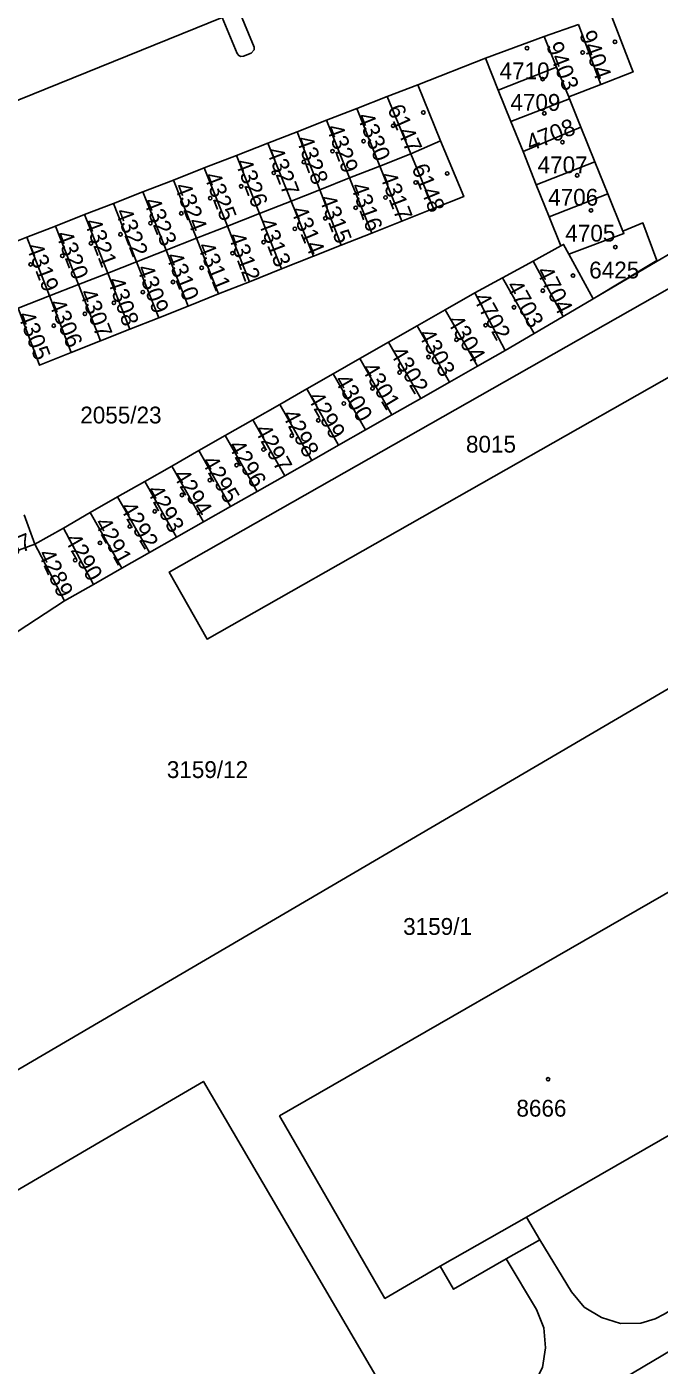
# Model space of a CAD drawing. Extents: x -564952 to -564307, y -1202373 to -1201847.
# Drawn here: x -564872.3 to -564808.4, y -1202052.1 to -1201916.7 of the extents above; entities that cross this region are included whole.
import ezdxf

# ---------------------------------------------------------------- set-up
doc = ezdxf.new("R2010")
doc.units = 0
for name, color, linetype in [('Hranice parcel', 7, 'Continuous'), ('Parcelní čísla', 7, 'Continuous'), ('Vnitřní kresba', 7, 'Continuous'), ('Značky budov', 7, 'Continuous')]:
    doc.layers.add(name, color=color, linetype=linetype)

msp = doc.modelspace()

# ---------------------------------------------------------------- linework, layer by layer
at = {"layer": 'Hranice parcel'}
for p, q in [((-564816.53, -1201916.48), (-564820.03, -1201917.7)), ((-564820.03, -1201917.7), (-564825.94, -1201919.91)), ((-564820.03, -1201917.7), (-564818.76, -1201920.82)), ((-564825.94, -1201919.91), (-564832.8, -1201922.58)), ((-564824.65, -1201923.12), (-564825.94, -1201919.91)), ((-564818.76, -1201920.82), (-564824.65, -1201923.12)), ((-564818.76, -1201920.82), (-564817.71, -1201923.35)), ((-564832.8, -1201922.58), (-564835.87, -1201923.78)), ((-564832.8, -1201922.58), (-564830.48, -1201928.24)), ((-564817.53, -1201923.8), (-564814.3, -1201922.55)), ((-564835.87, -1201923.78), (-564838.95, -1201924.98)), ((-564833.48, -1201929.57), (-564835.87, -1201923.78)), ((-564823.37, -1201926.3), (-564824.65, -1201923.12)), ((-564817.47, -1201924.01), (-564823.37, -1201926.3)), ((-564817.71, -1201923.35), (-564817.53, -1201923.8)), ((-564817.47, -1201924.01), (-564817.53, -1201923.8)), ((-564816.31, -1201926.87), (-564817.47, -1201924.01)), ((-564838.95, -1201924.98), (-564842.02, -1201926.18)), ((-564836.63, -1201930.81), (-564838.95, -1201924.98)), ((-564842.02, -1201926.18), (-564844.98, -1201927.33)), ((-564839.68, -1201932.01), (-564842.02, -1201926.18)), ((-564822.15, -1201929.34), (-564823.37, -1201926.3)), ((-564844.98, -1201927.33), (-564847.96, -1201928.5)), ((-564842.7, -1201933.2), (-564844.98, -1201927.33)), ((-564816.31, -1201926.87), (-564822.15, -1201929.34)), ((-564814.89, -1201930.38), (-564816.31, -1201926.87)), ((-564847.96, -1201928.5), (-564851.11, -1201929.73)), ((-564845.6, -1201934.34), (-564847.96, -1201928.5)), ((-564833.48, -1201929.57), (-564830.48, -1201928.24)), ((-564820.81, -1201932.69), (-564822.15, -1201929.34)), ((-564851.11, -1201929.73), (-564854.37, -1201931)), ((-564848.78, -1201935.59), (-564851.11, -1201929.73)), ((-564836.63, -1201930.81), (-564839.68, -1201932.01)), ((-564833.48, -1201929.57), (-564836.63, -1201930.81)), ((-564834.41, -1201936.38), (-564836.63, -1201930.81)), ((-564831.2, -1201935.1), (-564833.48, -1201929.57)), ((-564814.89, -1201930.38), (-564820.81, -1201932.69)), ((-564791.55, -1201930.35), (-564815.05, -1201944.22)), ((-564813.58, -1201933.62), (-564814.89, -1201930.38)), ((-564857.49, -1201932.22), (-564860.57, -1201933.42)), ((-564854.37, -1201931), (-564857.49, -1201932.22)), ((-564855.16, -1201938.1), (-564857.49, -1201932.22)), ((-564852.04, -1201936.87), (-564854.37, -1201931)), ((-564839.68, -1201932.01), (-564842.7, -1201933.2)), ((-564837.45, -1201937.59), (-564839.68, -1201932.01)), ((-564860.57, -1201933.42), (-564863.55, -1201934.59)), ((-564858.23, -1201939.31), (-564860.57, -1201933.42)), ((-564842.7, -1201933.2), (-564845.6, -1201934.34)), ((-564840.52, -1201938.81), (-564842.7, -1201933.2)), ((-564819.5, -1201935.94), (-564820.81, -1201932.69)), ((-564863.55, -1201934.59), (-564866.47, -1201935.72)), ((-564861.21, -1201940.48), (-564863.55, -1201934.59)), ((-564845.6, -1201934.34), (-564848.78, -1201935.59)), ((-564843.35, -1201939.93), (-564845.6, -1201934.34)), ((-564813.58, -1201933.62), (-564819.5, -1201935.94)), ((-564812.05, -1201937.38), (-564813.58, -1201933.62)), ((-564866.47, -1201935.72), (-564869.41, -1201936.87)), ((-564864.14, -1201941.63), (-564866.47, -1201935.72)), ((-564848.78, -1201935.59), (-564852.04, -1201936.87)), ((-564846.56, -1201941.21), (-564848.78, -1201935.59)), ((-564831.2, -1201935.1), (-564834.41, -1201936.38)), ((-564818.32, -1201938.88), (-564819.5, -1201935.94)), ((-564869.41, -1201936.87), (-564872.31, -1201938.01)), ((-564867.09, -1201942.79), (-564869.41, -1201936.87)), ((-564852.04, -1201936.87), (-564855.16, -1201938.1)), ((-564849.81, -1201942.5), (-564852.04, -1201936.87)), ((-564837.45, -1201937.59), (-564840.52, -1201938.81)), ((-564834.41, -1201936.38), (-564837.45, -1201937.59)), ((-564872.31, -1201938.01), (-564875.4, -1201939.21)), ((-564870.03, -1201943.94), (-564872.31, -1201938.01)), ((-564855.16, -1201938.1), (-564858.23, -1201939.31)), ((-564852.92, -1201943.74), (-564855.16, -1201938.1)), ((-564840.52, -1201938.81), (-564843.35, -1201939.93)), ((-564821.14, -1201940.42), (-564818.32, -1201938.88)), ((-564858.23, -1201939.31), (-564861.21, -1201940.48)), ((-564855.99, -1201944.96), (-564858.23, -1201939.31)), ((-564843.35, -1201939.93), (-564846.56, -1201941.21)), ((-564815.05, -1201944.22), (-564817.52, -1201939.7)), ((-564864.14, -1201941.63), (-564867.09, -1201942.79)), ((-564861.21, -1201940.48), (-564864.14, -1201941.63)), ((-564861.89, -1201947.31), (-564864.14, -1201941.63)), ((-564858.96, -1201946.14), (-564861.21, -1201940.48)), ((-564846.56, -1201941.21), (-564849.81, -1201942.5)), ((-564824.22, -1201942.1), (-564821.14, -1201940.42)), ((-564818.09, -1201946.01), (-564821.14, -1201940.42)), ((-564867.09, -1201942.79), (-564870.03, -1201943.94)), ((-564864.86, -1201948.49), (-564867.09, -1201942.79)), ((-564849.81, -1201942.5), (-564852.92, -1201943.74)), ((-564827.03, -1201943.64), (-564824.22, -1201942.1)), ((-564821.02, -1201947.73), (-564824.22, -1201942.1)), ((-564870.03, -1201943.94), (-564873.18, -1201945.18)), ((-564867.83, -1201949.67), (-564870.03, -1201943.94)), ((-564852.92, -1201943.74), (-564855.99, -1201944.96)), ((-564830.02, -1201945.35), (-564827.03, -1201943.64)), ((-564823.97, -1201949.47), (-564827.03, -1201943.64)), ((-564815.05, -1201944.22), (-564818.09, -1201946.01)), ((-564855.99, -1201944.96), (-564858.96, -1201946.14)), ((-564832.84, -1201946.96), (-564830.02, -1201945.35)), ((-564826.76, -1201951.05), (-564830.02, -1201945.35)), ((-564858.96, -1201946.14), (-564861.89, -1201947.31)), ((-564835.74, -1201948.62), (-564832.84, -1201946.96)), ((-564829.59, -1201952.66), (-564832.84, -1201946.96)), ((-564818.09, -1201946.01), (-564821.02, -1201947.73)), ((-564861.89, -1201947.31), (-564864.86, -1201948.49)), ((-564821.02, -1201947.73), (-564823.97, -1201949.47)), ((-564864.86, -1201948.49), (-564867.83, -1201949.67)), ((-564838.65, -1201950.27), (-564835.74, -1201948.62)), ((-564832.49, -1201954.3), (-564835.74, -1201948.62)), ((-564823.97, -1201949.47), (-564826.76, -1201951.05)), ((-564841.33, -1201951.81), (-564838.65, -1201950.27)), ((-564835.42, -1201955.97), (-564838.65, -1201950.27)), ((-564826.76, -1201951.05), (-564829.59, -1201952.66)), ((-564844.02, -1201953.34), (-564841.33, -1201951.81)), ((-564838.07, -1201957.48), (-564841.33, -1201951.81)), ((-564846.75, -1201954.9), (-564844.02, -1201953.34)), ((-564840.79, -1201959.02), (-564844.02, -1201953.34)), ((-564829.59, -1201952.66), (-564832.49, -1201954.3)), ((-564849.48, -1201956.46), (-564846.75, -1201954.9)), ((-564843.51, -1201960.57), (-564846.75, -1201954.9)), ((-564832.49, -1201954.3), (-564835.42, -1201955.97)), ((-564852.26, -1201958.05), (-564849.48, -1201956.46)), ((-564846.24, -1201962.12), (-564849.48, -1201956.46)), ((-564835.42, -1201955.97), (-564838.07, -1201957.48)), ((-564838.07, -1201957.48), (-564840.79, -1201959.02)), ((-564854.94, -1201959.58), (-564852.26, -1201958.05)), ((-564849.03, -1201963.7), (-564852.26, -1201958.05)), ((-564840.79, -1201959.02), (-564843.51, -1201960.57)), ((-564857.67, -1201961.14), (-564854.94, -1201959.58)), ((-564851.72, -1201965.23), (-564854.94, -1201959.58)), ((-564843.51, -1201960.57), (-564846.24, -1201962.12)), ((-564860.4, -1201962.7), (-564857.67, -1201961.14)), ((-564854.45, -1201966.78), (-564857.67, -1201961.14)), ((-564863.13, -1201964.26), (-564860.4, -1201962.7)), ((-564857.18, -1201968.33), (-564860.4, -1201962.7)), ((-564846.24, -1201962.12), (-564849.03, -1201963.7)), ((-564865.91, -1201965.85), (-564863.13, -1201964.26)), ((-564859.92, -1201969.88), (-564863.13, -1201964.26)), ((-564849.03, -1201963.7), (-564851.72, -1201965.23)), ((-564868.62, -1201967.41), (-564865.91, -1201965.85)), ((-564862.7, -1201971.46), (-564865.91, -1201965.85)), ((-564851.72, -1201965.23), (-564854.45, -1201966.78)), ((-564872.59, -1201966.08), (-564871.5, -1201969.04)), ((-564871.5, -1201969.04), (-564868.62, -1201967.41)), ((-564865.58, -1201973.1), (-564868.62, -1201967.41)), ((-564854.45, -1201966.78), (-564857.18, -1201968.33)), ((-564857.18, -1201968.33), (-564859.92, -1201969.88)), ((-564871.5, -1201969.04), (-564876.96, -1201971.05)), ((-564859.92, -1201969.88), (-564862.7, -1201971.46)), ((-564862.7, -1201971.46), (-564865.58, -1201973.1)), ((-564865.58, -1201973.1), (-564868.52, -1201974.75)), ((-564821.79, -1202037.08), (-564795.75, -1202022.1)), ((-564820.45, -1202039.38), (-564821.79, -1202037.08)), ((-564823.87, -1202041.31), (-564820.45, -1202039.38)), ((-564817.26, -1202044.62), (-564820.45, -1202039.38))]:
    msp.add_line(p, q, dxfattribs=at)
for points in [[(-564884.14, -1201928.55), (-564852.58, -1201915.77), (-564851.05, -1201919.42), (-564850.89, -1201919.63), (-564850.67, -1201919.72), (-564850.41, -1201919.7), (-564849.63, -1201919.4), (-564849.34, -1201919.07), (-564849.34, -1201918.79), (-564850.89, -1201915.06)], [(-564814.3, -1201922.55), (-564811.03, -1201921.29), (-564811.19, -1201920.88), (-564813.33, -1201915.28)], [(-564814.3, -1201922.55), (-564814.46, -1201922.12), (-564816.53, -1201916.48)], [(-564830.48, -1201928.24), (-564828.15, -1201933.89), (-564831.2, -1201935.1)], [(-564817.52, -1201939.7), (-564811.95, -1201937.64), (-564812.05, -1201937.38)], [(-564815.05, -1201944.22), (-564808.64, -1201940.36), (-564810.03, -1201936.56), (-564812.05, -1201937.38)], [(-564817.52, -1201939.7), (-564818.05, -1201938.73), (-564818.32, -1201938.88)], [(-564800.09, -1201939.05), (-564796.12, -1201945.76), (-564854.09, -1201978.63), (-564857.91, -1201971.86), (-564800.09, -1201939.05)], [(-564867.83, -1201949.67), (-564871.04, -1201950.95), (-564873.18, -1201945.18)], [(-564779.51, -1201950.78), (-564772.34, -1201963.08), (-564900.66, -1202038.24)], [(-564868.52, -1201974.75), (-564871.21, -1201969.6), (-564871.5, -1201969.04)], [(-564868.52, -1201974.75), (-564873.28, -1201977.89), (-564884.28, -1201983.8)], [(-564806.58, -1202003.73), (-564846.76, -1202026.84), (-564836.11, -1202045.3), (-564830.52, -1202042.04), (-564829.18, -1202044.37), (-564823.87, -1202041.31)], [(-564787.67, -1202019.66), (-564783.16, -1202027.51), (-564783, -1202028.26), (-564783.1, -1202029.51), (-564783.72, -1202031.45), (-564784.69, -1202033.14), (-564807.89, -1202046.9), (-564808.78, -1202047.36), (-564810.26, -1202047.79), (-564812.29, -1202047.82), (-564814.21, -1202047.24), (-564815.98, -1202046.17), (-564817.26, -1202044.62)], [(-564895.38, -1202047.31), (-564863.11, -1202028.42), (-564854.46, -1202023.35), (-564835.41, -1202055.88), (-564874.17, -1202078.58)], [(-564860.22, -1202082.01), (-564778.94, -1202033.78), (-564777.13, -1202032.93), (-564775.15, -1202032.6), (-564773.15, -1202032.93), (-564771.45, -1202034.01), (-564770.42, -1202035.04), (-564769.41, -1202036.32), (-564763.53, -1202046.19)], [(-564822.06, -1202055.29), (-564821.09, -1202054.07), (-564820.19, -1202052.29), (-564819.87, -1202050.29), (-564820.06, -1202048.28), (-564820.79, -1202046.43), (-564823.87, -1202041.31)]]:
    msp.add_lwpolyline(points, dxfattribs=at)
at = {"layer": 'Vnitřní kresba'}
msp.add_line((-564821.79, -1202037.08), (-564830.52, -1202042.04), dxfattribs=at)
at = {"layer": 'Značky budov'}
for centre in [(-564812.86, -1201918.25), (-564821.75, -1201918.89), (-564816.13, -1201919.32), (-564820.17, -1201922.01), (-564832.23, -1201925.39), (-564820, -1201925.48), (-564835.29, -1201926.73), (-564838.27, -1201928.29), (-564841.41, -1201929.31), (-564818.17, -1201928.39), (-564844.31, -1201930.4), (-564847.35, -1201931.5), (-564829.82, -1201931.55), (-564816.68, -1201931.75), (-564850.64, -1201932.85), (-564833, -1201932.47), (-564853.77, -1201934.05), (-564839.07, -1201935.02), (-564836.05, -1201933.99), (-564856.7, -1201935.59), (-564842.14, -1201936.09), (-564815.28, -1201935.29), (-564862.84, -1201937.71), (-564859.82, -1201936.58), (-564845.22, -1201937.15), (-564865.83, -1201938.62), (-564848.38, -1201938.5), (-564812.82, -1201939), (-564868.72, -1201939.88), (-564851.52, -1201939.62), (-564871.93, -1201940.75), (-564854.64, -1201941.1), (-564817.1, -1201941.88), (-564857.53, -1201942.53), (-564860.58, -1201943.55), (-564820.15, -1201943.41), (-564866.44, -1201945.75), (-564863.51, -1201944.63), (-564823.06, -1201945.09), (-564869.59, -1201946.95), (-564825.94, -1201946.9), (-564828.88, -1201948.36), (-564831.71, -1201950.11), (-564834.63, -1201951.68), (-564837.37, -1201953.29), (-564840.27, -1201954.81), (-564842.84, -1201956.52), (-564845.53, -1201958.07), (-564848.39, -1201959.47), (-564851.11, -1201961.05), (-564853.82, -1201962.57), (-564856.63, -1201964.07), (-564859.38, -1201965.72), (-564861.91, -1201967.24), (-564864.91, -1201968.91), (-564867.43, -1201970.65), (-564819.62, -1202023.14)]:
    msp.add_circle(centre, 0.175, dxfattribs=at)

# ---------------------------------------------------------------- texts
at = {"layer": 'Parcelní čísla'}
for s, rotation, p in [('9404', 290, (-564816.49, -1201917.45)), ('9403', 291, (-564819.84, -1201918.62)), ('6147', 294, (-564835.9, -1201925.02)), ('4329', 290, (-564842.06, -1201926.92)), ('4330', 292, (-564838.96, -1201925.79)), ('4708', 21, (-564821.42, -1201929.33)), ('4328', 290, (-564845.11, -1201928.08)), ('4327', 291, (-564848.1, -1201929.27)), ('4326', 291, (-564851.28, -1201930.42)), ('6148', 292, (-564833.45, -1201930.97)), ('4325', 291, (-564854.44, -1201931.79)), ('4317', 291, (-564836.67, -1201931.76)), ('4324', 291, (-564857.43, -1201932.86)), ('4316', 290, (-564839.61, -1201932.83)), ('4323', 292, (-564860.55, -1201934.38)), ('4315', 291, (-564842.8, -1201934.08)), ('4322', 291, (-564863.39, -1201935.42)), ('4314', 293, (-564845.68, -1201935.27)), ('4320', 291, (-564869.41, -1201937.72)), ('4321', 291, (-564866.53, -1201936.47)), ('4313', 291, (-564848.96, -1201936.45)), ('4319', 291, (-564872.4, -1201938.96)), ('4311', 292, (-564855.09, -1201938.89)), ('4312', 290, (-564851.98, -1201937.87)), ('4310', 292, (-564858.3, -1201939.91)), ('4309', 290, (-564861.22, -1201941.12)), ('4704', 297, (-564820.85, -1201941.45)), ('4308', 289, (-564864.18, -1201942.36)), ('4703', 299, (-564823.91, -1201942.91)), ('4307', 291, (-564867.01, -1201943.6)), ('4702', 299, (-564827.26, -1201944.17)), ('4305', 291, (-564873.25, -1201945.87)), ('4306', 293, (-564870.14, -1201944.68)), ('4304', 301, (-564829.91, -1201946.49)), ('4303', 298, (-564832.79, -1201947.81)), ('4302', 301, (-564835.68, -1201949.67)), ('4301', 301, (-564838.54, -1201951.28)), ('4300', 300, (-564841.27, -1201952.45)), ('4299', 300, (-564844.01, -1201954.21)), ('4298', 298, (-564846.56, -1201955.95)), ('4297', 299, (-564849.34, -1201957.48)), ('4296', 300, (-564852, -1201959.1)), ('4295', 300, (-564854.7, -1201960.68)), ('4294', 302, (-564857.6, -1201962.09)), ('4293', 299, (-564860.24, -1201963.62)), ('4292', 301, (-564862.97, -1201965.36)), ('4291', 299, (-564865.52, -1201966.89)), ('4287', 22, (-564876.35, -1201971.32)), ('4290', 300, (-564868.56, -1201968.55)), ('4289', 295, (-564871.21, -1201970))]:
    msp.add_text(s, height=1.7, rotation=rotation, dxfattribs=at).set_placement(p)
for s, p in [('4710', (-564824.52, -1201922.03)), ('4709', (-564823.43, -1201925.22)), ('4707', (-564820.68, -1201931.53)), ('4706', (-564819.61, -1201934.81)), ('4705', (-564817.88, -1201938.44)), ('6425', (-564815.46, -1201942.17)), ('2055/23', (-564866.91, -1201956.83)), ('8015', (-564827.92, -1201959.78)), ('3159/12', (-564858.16, -1201992.68)), ('3159/1', (-564834.27, -1202008.54)), ('8666', (-564822.82, -1202026.92))]:
    msp.add_text(s, height=1.7, dxfattribs=at).set_placement(p)

doc.saveas('drawing.dxf')
